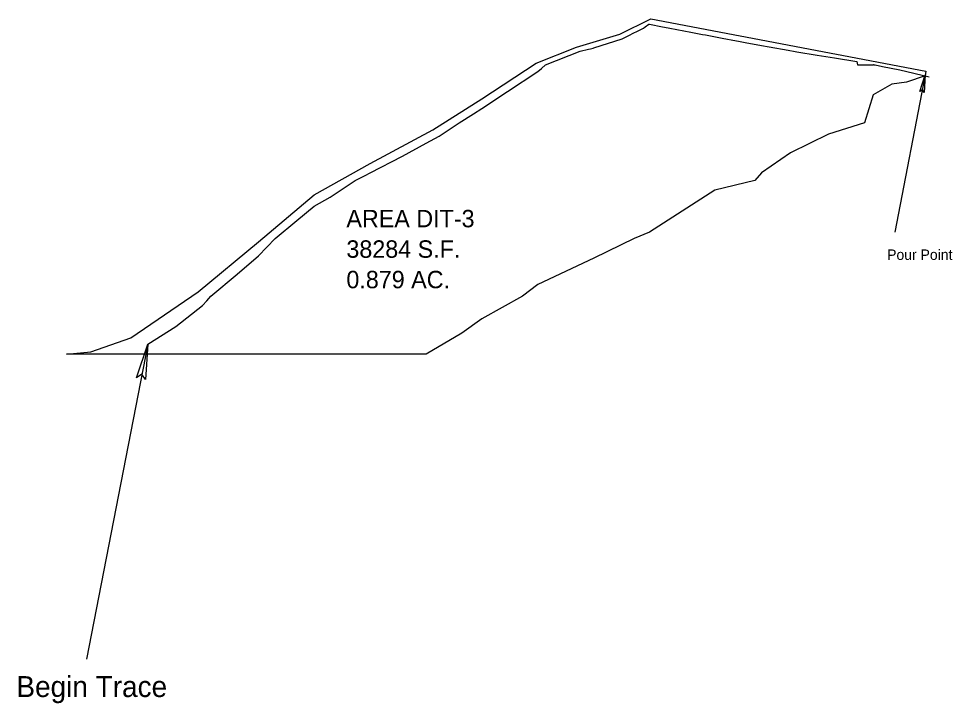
# Model space of a CAD drawing. Extents: x 3127 to 5445, y 2665 to 3371.
import ezdxf

# ---------------------------------------------------------------- set-up
doc = ezdxf.new("R2010")
doc.units = 0
for name, color, linetype in [('DESIGN - SCRATCH - User 1', 7, 'Continuous'), ('SURVEY - CENTERLINE - Preliminary', 7, 'Continuous'), ('SURVEY - CENTERLINE - Preliminary Text', 7, 'Continuous'), ('SURVEY - DRAINAGE - Area Shapes', 7, 'Continuous')]:
    doc.layers.add(name, color=color, linetype=linetype)

msp = doc.modelspace()

# ---------------------------------------------------------------- linework, layer by layer
at = {"layer": 'DESIGN - SCRATCH - User 1'}
msp.add_line((3647.24, 3026.29), (3629.71, 2935.84), dxfattribs=at)
msp.add_lwpolyline([(3647.24, 3026.29), (3646.56, 3016.18), (3645.58, 3017.7), (3644.05, 3016.67)], close=True, dxfattribs=at)
msp.add_lwpolyline([(3647.24, 3026.29), (3646.56, 3016.18), (3645.58, 3017.7), (3644.05, 3016.67), (3647.24, 3026.29)], dxfattribs=at)
at = {"layer": 'SURVEY - CENTERLINE - Preliminary'}
msp.add_lwpolyline([(3200.98, 2871.64), (3217.04, 2881.83), (3232.39, 2893.74), (3234.86, 2896.58), (3237.12, 2899.13), (3252.24, 2911.78), (3264.47, 2922.25), (3269.29, 2927.33), (3274.09, 2932.32), (3286.58, 2942.63), (3296.54, 2950.85), (3305.65, 2956.09), (3320.05, 2965.51), (3325.8, 2968.43), (3328.62, 2970.01), (3347.1, 2979.57), (3360.7, 2986.94), (3368.18, 2990.96), (3379.62, 2998.69), (3387.85, 3003.79), (3392.78, 3006.94), (3407.51, 3016.63), (3424.85, 3028.08), (3426.87, 3029.8), (3429.24, 3031.88), (3449.24, 3039.84), (3453.91, 3040.93), (3455.13, 3041.22), (3456.53, 3041.55), (3456.93, 3041.65), (3473.18, 3046.91), (3474.06, 3047.35), (3477.37, 3048.99), (3479.49, 3050.06), (3482.12, 3051.38), (3485.46, 3053.07), (3486.48, 3053.81), (3488.63, 3055.36), (3489.01, 3055.29), (3489.86, 3055.12), (3495.49, 3054.04), (3500.62, 3053.06), (3512.72, 3050.73), (3519.32, 3049.47), (3521.08, 3049.13), (3530.57, 3047.32), (3538.96, 3045.71), (3539.97, 3045.53), (3540.1, 3045.51), (3543.89, 3044.84), (3553.16, 3043.16), (3557.53, 3042.37), (3568.49, 3040.39), (3572.49, 3039.66), (3573.41, 3039.49), (3585.13, 3037.58), (3595.06, 3035.96), (3607.96, 3033.86), (3608.32, 3031.88), (3617.32, 3031.88), (3617.44, 3032.08), (3617.77, 3032.02), (3618.49, 3031.88), (3622.7, 3031.07), (3627.61, 3030.12), (3632.52, 3029.16), (3649.39, 3025.12)], dxfattribs=at)
at = {"layer": 'SURVEY - CENTERLINE - Preliminary Text'}
msp.add_line((3200.98, 2871.64), (3165.91, 2690.75), dxfattribs=at)
msp.add_lwpolyline([(3200.98, 2871.64), (3199.61, 2851.44), (3197.65, 2854.46), (3194.6, 2852.41)], close=True, dxfattribs=at)
msp.add_lwpolyline([(3200.98, 2871.64), (3199.61, 2851.44), (3197.65, 2854.46), (3194.6, 2852.41), (3200.98, 2871.64)], dxfattribs=at)
at = {"layer": 'SURVEY - DRAINAGE - Area Shapes'}
for p, q in [((3489.69, 3058.47), (3647.55, 3028.27)), ((3360.7, 2865.94), (3154.26, 2865.94))]:
    msp.add_line(p, q, dxfattribs=at)
for points in [[(3154.26, 2865.94), (3168.24, 2867.29), (3191.27, 2875.3), (3230.01, 2901.59), (3264.47, 2930.4), (3296.54, 2957.27), (3328.62, 2975.43), (3364.67, 2994.58), (3392.78, 3012.49), (3423.88, 3032.88), (3446.98, 3042.18), (3471.93, 3049.55), (3489.69, 3058.47)], [(3647.55, 3028.27), (3647.15, 3025.66), (3636.51, 3021.95), (3627.93, 3020.9), (3617.32, 3014.67), (3612.25, 2998.69), (3591.6, 2992.11), (3569.79, 2981.49), (3553.16, 2970.05), (3549.42, 2965.51), (3526.44, 2959.96), (3489.01, 2935.87), (3480.18, 2932.32), (3456.93, 2921.01), (3424.85, 2905.84), (3416.09, 2899.13), (3392.78, 2886.19), (3381.23, 2877.89), (3360.7, 2865.94)]]:
    msp.add_lwpolyline(points, dxfattribs=at)

# ---------------------------------------------------------------- texts
at = {"layer": 'DESIGN - SCRATCH - User 1'}
msp.add_text('Pour Point', height=6, dxfattribs=at).set_placement((3625.33, 2920))
at = {"layer": 'SURVEY - CENTERLINE - Preliminary Text'}
msp.add_text('Begin Trace', height=12, dxfattribs=at).set_placement((3125.59, 2669.1))
at = {"layer": 'SURVEY - DRAINAGE - Area Shapes'}
for s, p in [('AREA DIT-3', (3314.98, 2938.73)), ('38284 S.F.', (3314.98, 2921.23)), ('0.879 AC.', (3314.98, 2903.73))]:
    msp.add_text(s, height=10, dxfattribs=at).set_placement(p)

doc.saveas('drawing.dxf')
